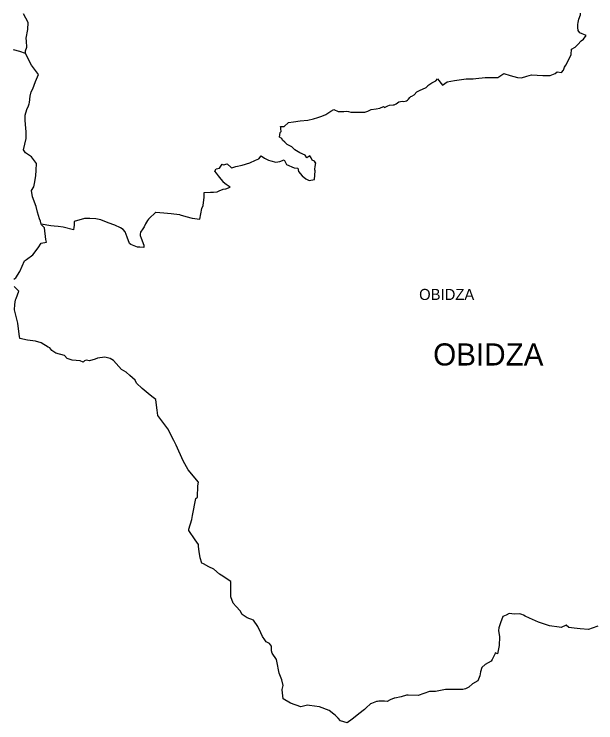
# Model space of a CAD drawing. Extents: x -562952 to -547638, y 190691 to 208158.
# Drawn here: x -556696 to -551969, y 190691 to 196451 of the extents above; entities that cross this region are included whole.
import ezdxf

# ---------------------------------------------------------------- set-up
doc = ezdxf.new("R2010")
doc.units = 0
for name, color, linetype in [('granica_gminy', 7, 'Continuous'), ('granica_sołectwa', 7, 'Continuous'), ('nazwy miejscowości', 7, 'Continuous'), ('nazwy miejscowości DUŻE', 7, 'Continuous'), ('obwódka', 7, 'Continuous')]:
    doc.layers.add(name, color=color, linetype=linetype)

msp = doc.modelspace()

# ---------------------------------------------------------------- linework, layer by layer
at = {"layer": 'granica_gminy'}
for points in [[(-556697.4, 194298.2), (-556681, 194307.6), (-556650, 194359.1), (-556611, 194446.5), (-556594.6, 194457.9), (-556544.3, 194494.8), (-556501.4, 194551.1), (-556476.7, 194589.6), (-556433.2, 194598.8), (-556439.1, 194620), (-556448.4, 194715), (-556473.7, 194739.7), (-556477, 194744.8), (-556482.9, 194768.3), (-556488.9, 194788), (-556507, 194842), (-556518.1, 194888.8), (-556546.1, 194967.5), (-556555.3, 195018), (-556536.5, 195048.6), (-556531.2, 195075.8), (-556519.1, 195138.2), (-556516.3, 195184.5), (-556513.4, 195238.6), (-556555.3, 195290.8), (-556602.4, 195325.2), (-556619.1, 195348.9), (-556597.8, 195439.8), (-556598.1, 195495.2), (-556601.5, 195524.9), (-556607, 195585.9), (-556607.3, 195630.7), (-556592.9, 195676.7), (-556578.5, 195705), (-556573.6, 195722.2), (-556571.6, 195734.2), (-556565.3, 195785.1), (-556556.9, 195821.3), (-556544.4, 195843.8), (-556522.1, 195904.6), (-556499, 195961.2), (-556514.1, 195981.9), (-556553.7, 196036.3), (-556603.3, 196132.7), (-556649, 196146.8), (-556701.3, 196160.3)], [(-551954.3, 191476.3), (-551997.7, 191461), (-552029.3, 191450.9), (-552097.5, 191456.3), (-552144.7, 191461.9), (-552189.2, 191467.4), (-552211.3, 191485.3), (-552250.1, 191467.3), (-552267.8, 191469), (-552345.9, 191479.9), (-552435.5, 191508.9), (-552508, 191542.2), (-552544.6, 191558.6), (-552556.3, 191565.3), (-552569.3, 191570.7), (-552586.1, 191577.9), (-552630.9, 191575.3), (-552672.4, 191579.7), (-552699.1, 191567.6), (-552725.7, 191555.4), (-552744.6, 191504.2), (-552757.5, 191464.6), (-552759.1, 191442.9), (-552752.9, 191391.6), (-552754.3, 191319.2), (-552768.5, 191253.4), (-552786.3, 191259.7), (-552791, 191248.9), (-552812.4, 191206.9), (-552820.6, 191191.6), (-552868.5, 191165.2), (-552896.5, 191141.5), (-552906.7, 191104.8), (-552911.3, 191074.4), (-552929.3, 191033.4), (-552971.5, 191008.5), (-553002.1, 190982.3), (-553027.3, 190968.7), (-553049.4, 190961.1), (-553104.4, 190962), (-553190.5, 190961.6), (-553272.6, 190946), (-553319.5, 190946), (-553413.6, 190914.8), (-553494.9, 190916.2), (-553508.6, 190916), (-553550.5, 190902.9), (-553601.2, 190893), (-553607.8, 190891.5), (-553640, 190877.9), (-553665.3, 190865.9), (-553687.4, 190866.2), (-553732.7, 190866.7), (-553742.7, 190865.5), (-553751, 190863.6), (-553791.2, 190848.6), (-553801, 190844.5), (-553835.3, 190811.9), (-553848.9, 190799.7), (-553896.4, 190764.3), (-553925.9, 190740.6), (-553949.8, 190720.1), (-553990.5, 190691.4), (-554043, 190708.6), (-554063.6, 190728.9), (-554087.6, 190753.3), (-554098.8, 190762.2), (-554135.8, 190790.4), (-554216, 190821), (-554295.7, 190832), (-554310.9, 190834.7), (-554365.4, 190821.5), (-554450.5, 190851.5), (-554509.2, 190886.1), (-554518.3, 190959.1), (-554518.7, 190961.2), (-554510.5, 190994.3), (-554521.1, 191041.4), (-554543, 191096.2), (-554550.6, 191135.6), (-554553.6, 191151.3), (-554564.3, 191205.9), (-554599.2, 191257.9), (-554605.5, 191276), (-554605, 191314), (-554620, 191336.8), (-554646.8, 191349), (-554657.6, 191366), (-554676.8, 191393.4), (-554690.2, 191421.5), (-554715.2, 191474.3), (-554751.9, 191524.7), (-554801.2, 191545), (-554843.3, 191571.1), (-554859.3, 191600.4), (-554890.9, 191635.8), (-554916.7, 191663.8), (-554936.3, 191714.9), (-554934.1, 191778.9), (-554935.1, 191838.8), (-555012.5, 191891.7), (-555026.3, 191900.7), (-555073.5, 191939), (-555113.7, 191960.6), (-555156.6, 191983.3), (-555169.5, 191989.2), (-555185.2, 192033), (-555193.2, 192083.9), (-555198, 192123.4), (-555198.6, 192139.5), (-555224.8, 192179.7), (-555277.2, 192255.6), (-555277.2, 192264.8), (-555252.2, 192344.2), (-555246.3, 192376.3), (-555220.9, 192514.1), (-555205.7, 192525.2), (-555203.7, 192617.8), (-555197.7, 192646.5), (-555283.1, 192747.4), (-555321.2, 192822), (-555378.9, 192947.4), (-555398.8, 192986.6), (-555447.6, 193082.2), (-555488.1, 193134.8), (-555528.6, 193190), (-555534.2, 193232.9), (-555539.3, 193274.1), (-555544.7, 193319.1), (-555576.2, 193344.6), (-555607.8, 193369.1), (-555655, 193409.8), (-555702.9, 193451.5), (-555713.7, 193477.3), (-555755.7, 193514.6), (-555786, 193541.3), (-555823.5, 193562.5), (-555889.3, 193637.2), (-555914.8, 193652), (-555959.4, 193664), (-556019.9, 193654.7), (-556037.8, 193646.1), (-556084.7, 193633.9), (-556112.1, 193639.8), (-556124, 193632.4), (-556135.6, 193624), (-556159.8, 193634.2), (-556224, 193639.2), (-556265.4, 193653.8), (-556287.1, 193676.8), (-556357.6, 193697.2), (-556391, 193717.8), (-556405.9, 193738.4), (-556420.8, 193745.2), (-556475.8, 193780.3), (-556521.3, 193794.3), (-556588.1, 193800.8), (-556649.1, 193815.7), (-556654.5, 193849.1), (-556664.9, 193939.8), (-556694.1, 194049.4), (-556689.3, 194092.2), (-556686.1, 194129.7), (-556680.7, 194141.5), (-556659.2, 194199.1), (-556696.8, 194238.3)]]:
    msp.add_lwpolyline(points, dxfattribs=at)
at = {"layer": 'granica_sołectwa'}
for points in [[(-556603.3, 196132.7), (-556603.3, 196153.8), (-556592.2, 196184.1), (-556595, 196232), (-556597.2, 196257.3), (-556583.7, 196325.7), (-556583.2, 196382.2), (-556620.9, 196454.9)], [(-553335, 195872.8), (-553301.1, 195893.7), (-553290.8, 195898.4), (-553279.4, 195902.7), (-553268.3, 195910), (-553255, 195924.7), (-553215.8, 195874.4), (-553176.4, 195900.9), (-553117.6, 195912.7), (-553022.8, 195924.9), (-553006.2, 195926.4), (-552966.3, 195925.3), (-552944.8, 195927.9), (-552868.5, 195935.8), (-552824.2, 195936.5), (-552764.6, 195937.8), (-552718.1, 195970.1), (-552664.9, 195954), (-552606.4, 195935.3), (-552573.1, 195934.2), (-552528.7, 195947.4), (-552491, 195958.1), (-552400.1, 195954), (-552339.3, 195951.5), (-552298.6, 195968.5), (-552282.4, 195982.9), (-552247.1, 195977.9), (-552233.1, 195996.4), (-552224.7, 196019.3), (-552213.2, 196035.6), (-552186.3, 196088.4), (-552170.5, 196124.4), (-552166.9, 196167.6), (-552137.4, 196182.3), (-552115.1, 196203.7), (-552087.7, 196233.3), (-552069.9, 196248.1), (-552047.4, 196277.2), (-552099.4, 196298.6), (-552113.7, 196319.2), (-552116.5, 196343.7), (-552114.7, 196366.5), (-552112.6, 196382.3), (-552106.2, 196411.4), (-552094.3, 196444.8), (-552094.9, 196459.6)], [(-554528.5, 195527.4), (-554531.8, 195537), (-554502.4, 195537.6), (-554467.3, 195570.7), (-554425.4, 195576.5), (-554373.1, 195583.3), (-554309.5, 195589.1), (-554263, 195599.8), (-554229.2, 195610.7), (-554196.7, 195623.1), (-554163.1, 195636.2), (-554123.5, 195663.9), (-554097.9, 195677.2), (-554063.8, 195660.3), (-554015.7, 195660.2), (-553991.3, 195661.7), (-553979.5, 195660.6), (-553959.9, 195654.8), (-553924.8, 195654.1), (-553877.9, 195653.6), (-553845.6, 195653.6), (-553820.9, 195662.4), (-553794.7, 195676.7), (-553754.2, 195681.1), (-553723.5, 195686.5), (-553693.7, 195701.6), (-553686.3, 195693), (-553658.6, 195706.9), (-553644.7, 195712.7), (-553616.7, 195713.4), (-553606.7, 195714.7), (-553592.5, 195721.9), (-553569.4, 195738.3), (-553556.7, 195742.7), (-553543.8, 195743.7), (-553530.3, 195742.4), (-553519.6, 195744.1), (-553506.4, 195748.1), (-553499.8, 195752.2), (-553491.4, 195759.9), (-553480, 195772.9), (-553473, 195780.9), (-553465.7, 195785.4), (-553446.3, 195794.6), (-553422.6, 195819.6), (-553395.7, 195833.8), (-553378.5, 195842.6), (-553348.7, 195856.5), (-553341.4, 195861), (-553337.5, 195866.4), (-553335, 195872.8)], [(-555544.4, 194843), (-555479.3, 194836.1), (-555420.4, 194832.2), (-555353, 194822.8), (-555347.4, 194819.3), (-555301.7, 194807.9), (-555249.8, 194793.4), (-555185.8, 194784.9), (-555170.5, 194873), (-555158.7, 194895.5), (-555150.6, 194962.7), (-555151.9, 195002.1), (-555101.3, 195003.7), (-555075.6, 195004.4), (-555046.3, 195007.3), (-555030.6, 195014.6), (-554997, 195028.1), (-554974.8, 195031.3), (-554939.5, 195046.2), (-554973.3, 195065.6), (-554996.7, 195086), (-554998, 195092), (-555014.1, 195110.2), (-555034.2, 195136.4), (-555051, 195157.9), (-555064.7, 195176.2), (-555053.7, 195194.4), (-555028.3, 195200.7), (-555006.7, 195231.1), (-554996, 195227.4), (-554963.7, 195233.9), (-554932.7, 195205.6), (-554927.9, 195201.4), (-554893.6, 195211.9), (-554844, 195225.1), (-554781.1, 195243.1), (-554734.9, 195263.4), (-554708.5, 195276.6), (-554688.2, 195300.4), (-554660.5, 195280.3), (-554629.5, 195264.6), (-554610.8, 195259.5), (-554569, 195249), (-554537.7, 195253.9), (-554502.5, 195267.3), (-554481.9, 195228.4), (-554420.9, 195202.2), (-554392, 195199.3), (-554384, 195173.7), (-554355.2, 195137.3), (-554326.9, 195113.1), (-554298.4, 195098.2), (-554255.9, 195107.6), (-554250.3, 195178.8), (-554251.5, 195184.9), (-554252.9, 195190.8), (-554251.1, 195212.2), (-554244.9, 195241.9), (-554247, 195242.3), (-554254.6, 195256.6), (-554275.6, 195265.8), (-554282.4, 195283.1), (-554294.5, 195298.9), (-554317.4, 195284.5), (-554331.6, 195304.5), (-554375.7, 195325.5), (-554413.9, 195347.9), (-554439, 195372.4), (-554476.3, 195391.8), (-554496.6, 195411.7), (-554515.1, 195427.9), (-554521.6, 195441.4), (-554539.5, 195452.3), (-554533.7, 195488.2), (-554527.5, 195498), (-554528.3, 195520.3), (-554528.5, 195527.4)], [(-555544.4, 194843), (-555554.3, 194831.5), (-555590.2, 194798.7), (-555603.1, 194786.2), (-555611.8, 194773.4), (-555627.4, 194747.5), (-555639.6, 194724), (-555650.9, 194706.8), (-555668.1, 194679.3), (-555672.5, 194663.9), (-555672.8, 194651), (-555664.3, 194631.6), (-555643.1, 194572.8), (-555641.2, 194553.6)], [(-555641.2, 194553.6), (-555673.7, 194558.2), (-555693.7, 194556.7), (-555746.5, 194577.9), (-555759.6, 194588.2), (-555778.4, 194639.4), (-555794.4, 194682.2), (-555811.3, 194701.3), (-555832.3, 194715.1), (-555878.9, 194735.4), (-555931.8, 194756.4), (-555991, 194779.6), (-556033, 194787.1), (-556080.4, 194791), (-556124.2, 194789.6), (-556208.4, 194765.9), (-556208.5, 194754.2), (-556209.4, 194734.7), (-556212.2, 194720.3), (-556213.9, 194699.4), (-556298.5, 194719.7), (-556338.8, 194724.4), (-556371.3, 194728.1), (-556397.8, 194731.3), (-556476.4, 194743.9)]]:
    msp.add_lwpolyline(points, dxfattribs=at)
at = {"layer": 'obwódka'}
for points in [[(-556697.4, 194298.2), (-556681, 194307.6), (-556650, 194359.1), (-556611, 194446.5), (-556594.6, 194457.9), (-556544.3, 194494.8), (-556501.4, 194551.1), (-556476.7, 194589.6), (-556433.2, 194598.8), (-556439.1, 194620), (-556448.4, 194715), (-556473.7, 194739.7), (-556477, 194744.8), (-556482.9, 194768.3), (-556488.9, 194788), (-556507, 194842), (-556518.1, 194888.8), (-556546.1, 194967.5), (-556555.3, 195018), (-556536.5, 195048.6), (-556531.2, 195075.8), (-556519.1, 195138.2), (-556516.3, 195184.5), (-556513.4, 195238.6), (-556555.3, 195290.8), (-556602.4, 195325.2), (-556619.1, 195348.9), (-556597.8, 195439.8), (-556598.1, 195495.2), (-556601.5, 195524.9), (-556607, 195585.9), (-556607.3, 195630.7), (-556592.9, 195676.7), (-556578.5, 195705), (-556573.6, 195722.2), (-556571.6, 195734.2), (-556565.3, 195785.1), (-556556.9, 195821.3), (-556544.4, 195843.8), (-556522.1, 195904.6), (-556499, 195961.2), (-556514.1, 195981.9), (-556553.7, 196036.3), (-556603.3, 196132.7), (-556649, 196146.8), (-556701.3, 196160.3)], [(-551954.3, 191476.3), (-551997.7, 191461), (-552029.3, 191450.9), (-552097.5, 191456.3), (-552144.7, 191461.9), (-552189.2, 191467.4), (-552211.3, 191485.3), (-552250.1, 191467.3), (-552267.8, 191469), (-552345.9, 191479.9), (-552435.5, 191508.9), (-552508, 191542.2), (-552544.6, 191558.6), (-552556.3, 191565.3), (-552569.3, 191570.7), (-552586.1, 191577.9), (-552630.9, 191575.3), (-552672.4, 191579.7), (-552699.1, 191567.6), (-552725.7, 191555.4), (-552744.6, 191504.2), (-552757.5, 191464.6), (-552759.1, 191442.9), (-552752.9, 191391.6), (-552754.3, 191319.2), (-552768.5, 191253.4), (-552786.3, 191259.7), (-552791, 191248.9), (-552812.4, 191206.9), (-552820.6, 191191.6), (-552868.5, 191165.2), (-552896.5, 191141.5), (-552906.7, 191104.8), (-552911.3, 191074.4), (-552929.3, 191033.4), (-552971.5, 191008.5), (-553002.1, 190982.3), (-553027.3, 190968.7), (-553049.4, 190961.1), (-553104.4, 190962), (-553190.5, 190961.6), (-553272.6, 190946), (-553319.5, 190946), (-553413.6, 190914.8), (-553494.9, 190916.2), (-553508.6, 190916), (-553550.5, 190902.9), (-553601.2, 190893), (-553607.8, 190891.5), (-553640, 190877.9), (-553665.3, 190865.9), (-553687.4, 190866.2), (-553732.7, 190866.7), (-553742.7, 190865.5), (-553751, 190863.6), (-553791.2, 190848.6), (-553801, 190844.5), (-553835.3, 190811.9), (-553848.9, 190799.7), (-553896.4, 190764.3), (-553925.9, 190740.6), (-553949.8, 190720.1), (-553990.5, 190691.4), (-554043, 190708.6), (-554063.6, 190728.9), (-554087.6, 190753.3), (-554098.8, 190762.2), (-554135.8, 190790.4), (-554216, 190821), (-554295.7, 190832), (-554310.9, 190834.7), (-554365.4, 190821.5), (-554450.5, 190851.5), (-554509.2, 190886.1), (-554518.3, 190959.1), (-554518.7, 190961.2), (-554510.5, 190994.3), (-554521.1, 191041.4), (-554543, 191096.2), (-554550.6, 191135.6), (-554553.6, 191151.3), (-554564.3, 191205.9), (-554599.2, 191257.9), (-554605.5, 191276), (-554605, 191314), (-554620, 191336.8), (-554646.8, 191349), (-554657.6, 191366), (-554676.8, 191393.4), (-554690.2, 191421.5), (-554715.2, 191474.3), (-554751.9, 191524.7), (-554801.2, 191545), (-554843.3, 191571.1), (-554859.3, 191600.4), (-554890.9, 191635.8), (-554916.7, 191663.8), (-554936.3, 191714.9), (-554934.1, 191778.9), (-554935.1, 191838.8), (-555012.5, 191891.7), (-555026.3, 191900.7), (-555073.5, 191939), (-555113.7, 191960.6), (-555156.6, 191983.3), (-555169.5, 191989.2), (-555185.2, 192033), (-555193.2, 192083.9), (-555198, 192123.4), (-555198.6, 192139.5), (-555224.8, 192179.7), (-555277.2, 192255.6), (-555277.2, 192264.8), (-555252.2, 192344.2), (-555246.3, 192376.3), (-555220.9, 192514.1), (-555205.7, 192525.2), (-555203.7, 192617.8), (-555197.7, 192646.5), (-555283.1, 192747.4), (-555321.2, 192822), (-555378.9, 192947.4), (-555398.8, 192986.6), (-555447.6, 193082.2), (-555488.1, 193134.8), (-555528.6, 193190), (-555534.2, 193232.9), (-555539.3, 193274.1), (-555544.7, 193319.1), (-555576.2, 193344.6), (-555607.8, 193369.1), (-555655, 193409.8), (-555702.9, 193451.5), (-555713.7, 193477.3), (-555755.7, 193514.6), (-555786, 193541.3), (-555823.5, 193562.5), (-555889.3, 193637.2), (-555914.8, 193652), (-555959.4, 193664), (-556019.9, 193654.7), (-556037.8, 193646.1), (-556084.7, 193633.9), (-556112.1, 193639.8), (-556124, 193632.4), (-556135.6, 193624), (-556159.8, 193634.2), (-556224, 193639.2), (-556265.4, 193653.8), (-556287.1, 193676.8), (-556357.6, 193697.2), (-556391, 193717.8), (-556405.9, 193738.4), (-556420.8, 193745.2), (-556475.8, 193780.3), (-556521.3, 193794.3), (-556588.1, 193800.8), (-556649.1, 193815.7), (-556654.5, 193849.1), (-556664.9, 193939.8), (-556694.1, 194049.4), (-556689.3, 194092.2), (-556686.1, 194129.7), (-556680.7, 194141.5), (-556659.2, 194199.1), (-556696.8, 194238.3)]]:
    msp.add_lwpolyline(points, dxfattribs=at)

# ---------------------------------------------------------------- texts
at = {"layer": 'nazwy miejscowości'}
msp.add_text('OBIDZA', height=90, dxfattribs=at).set_placement((-553405.2, 194128.2))
at = {"layer": 'nazwy miejscowości DUŻE'}
msp.add_text('OBIDZA', height=180, dxfattribs=at).set_placement((-553290.9, 193595.6))

doc.saveas('drawing.dxf')
